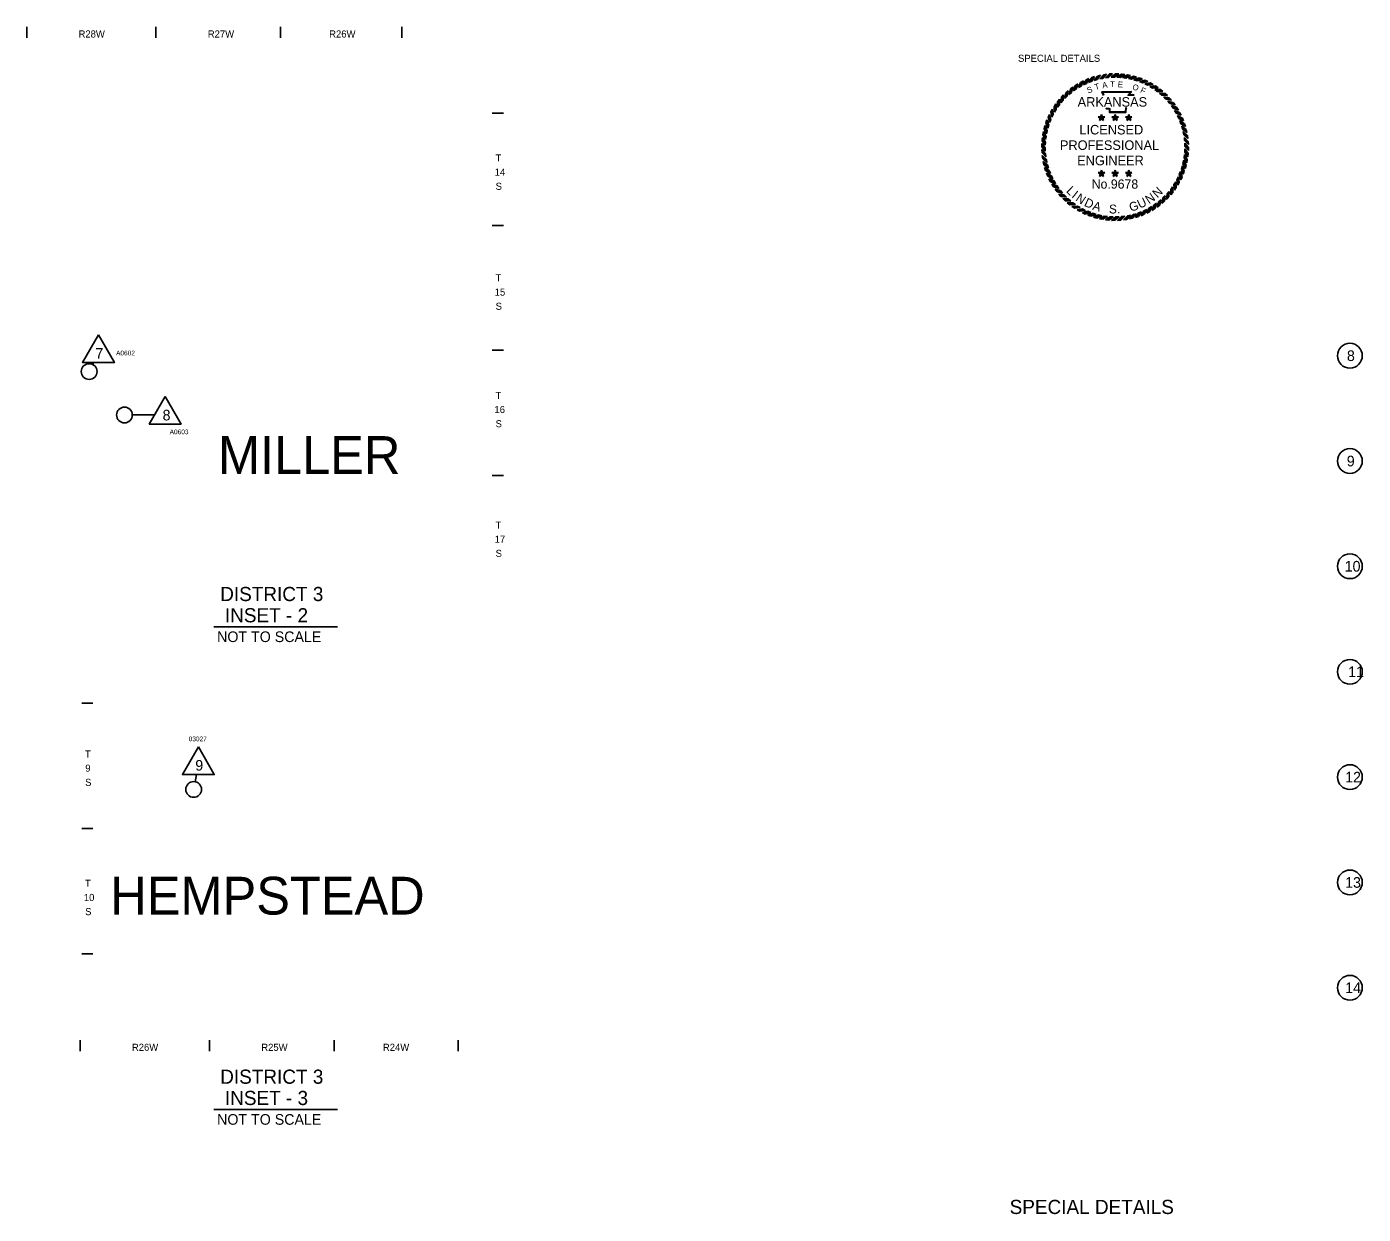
# Model space of a CAD drawing. Extents: x -17742 to 32032, y -17264 to 5867.
# Drawn here: x 7189 to 18510, y -4264 to 5793 of the extents above; entities that cross this region are included whole.
import ezdxf

# ---------------------------------------------------------------- set-up
doc = ezdxf.new("R2010")
doc.units = 0
for name, color, linetype in [('2', 7, 'Continuous'), ('Default', 7, 'Continuous'), ('R_Annotation', 7, 'Continuous'), ('R_Border', 7, 'Continuous'), ('R_No Plot', 7, 'Continuous'), ('STAMP', 7, 'Continuous')]:
    doc.layers.add(name, color=color, linetype=linetype)

msp = doc.modelspace()

# ---------------------------------------------------------------- linework, layer by layer
at = {"layer": 'Default'}
for p, q in [((7189, 5793), (7189, 5698)), ((8284, 5793), (8284, 5698)), ((9340, 5793), (9340, 5698)), ((10367, 5793), (10367, 5698)), ((11227, 5062), (11132, 5062)), ((11227, 4110), (11132, 4110)), ((11227, 3054), (11132, 3054)), ((11227, 1992), (11132, 1992)), ((7750, 65), (7655, 65)), ((7750, -997), (7655, -997)), ((7750, -2058), (7655, -2058)), ((7642, -2789), (7642, -2884)), ((8737, -2789), (8737, -2884)), ((9793, -2789), (9793, -2884)), ((10843, -2789), (10843, -2884))]:
    msp.add_line(p, q, dxfattribs=at)
at = {"layer": 'R_Annotation'}
for p, q in [((7748, 2933), (7756, 2949)), ((8083, 2505), (8272, 2505)), ((8773, 711), (9823, 711)), ((8616, -601), (8628, -539)), ((8773, -3377), (9823, -3377))]:
    msp.add_line(p, q, dxfattribs=at)
for points in [[(7797, 3183), (7932, 2949), (7662, 2949)], [(8362, 2662), (8497, 2428), (8227, 2428)], [(8643, -306), (8778, -540), (8508, -540)]]:
    msp.add_lwpolyline(points, close=True, dxfattribs=at)
for centre, radius in [((18397, 3007), 105), ((7718, 2873), 66.7), ((8017, 2505), 66.7), ((18397, 2115), 105), ((18397, 1224), 105), ((18397, 330), 105), ((18397, -562), 105), ((8603, -666), 66.7), ((18397, -1454), 105), ((18397, -2346), 105)]:
    msp.add_circle(centre, radius, dxfattribs=at)
at = {"layer": 'STAMP'}
for p, q in [((16116, 5321), (16140, 5334)), ((16162, 5343), (16187, 5355)), ((16184, 5322), (16210, 5331)), ((16210, 5362), (16235, 5371)), ((16230, 5339), (16257, 5346)), ((16259, 5376), (16285, 5383)), ((16278, 5352), (16305, 5356)), ((16309, 5387), (16336, 5391)), ((16326, 5360), (16353, 5363)), ((16360, 5393), (16387, 5395)), ((16375, 5365), (16402, 5365)), ((16412, 5394), (16439, 5394)), ((16423, 5366), (16451, 5364)), ((16463, 5392), (16490, 5390)), ((16472, 5363), (16499, 5358)), ((16513, 5385), (16540, 5381)), ((16521, 5355), (16547, 5349)), ((16564, 5375), (16590, 5368)), ((16568, 5344), (16594, 5335)), ((16613, 5360), (16638, 5351)), ((16615, 5329), (16640, 5318)), ((16660, 5341), (16685, 5330)), ((15954, 5197), (15972, 5217)), ((15990, 5233), (16010, 5251)), ((16019, 5220), (16040, 5237)), ((16030, 5266), (16051, 5282)), ((16057, 5250), (16079, 5266)), ((16072, 5295), (16094, 5310)), ((16097, 5278), (16121, 5291)), ((16140, 5302), (16165, 5313)), ((16660, 5310), (16684, 5297)), ((16703, 5287), (16726, 5273)), ((16706, 5318), (16730, 5305)), ((16745, 5261), (16766, 5245)), ((16750, 5292), (16773, 5277)), ((16784, 5232), (16804, 5213)), ((16792, 5262), (16813, 5245)), ((16831, 5228), (16851, 5210)), ((15864, 5072), (15877, 5096)), ((15891, 5116), (15905, 5139)), ((15921, 5158), (15937, 5179)), ((15921, 5111), (15938, 5132)), ((15950, 5150), (15969, 5170)), ((15983, 5186), (16003, 5205)), ((16820, 5199), (16839, 5179)), ((16854, 5164), (16871, 5142)), ((16867, 5192), (16885, 5172)), ((16885, 5126), (16900, 5103)), ((16900, 5153), (16917, 5131)), ((16929, 5111), (16944, 5088)), ((15822, 4978), (15831, 5004)), ((15841, 5026), (15852, 5051)), ((15853, 4981), (15864, 5006)), ((15872, 5026), (15885, 5050)), ((15895, 5069), (15910, 5092)), ((16320, 5031), (16265, 5031)), ((16265, 5031), (16310, 4999)), ((16293, 5051), (16276, 4999)), ((16276, 4999), (16320, 5031)), ((16289, 5022), (16297, 5022)), ((16310, 4999), (16293, 5051)), ((16293, 5025), (16293, 5018)), ((16436, 5031), (16381, 5031)), ((16381, 5031), (16425, 4999)), ((16408, 5051), (16391, 4999)), ((16391, 4999), (16436, 5031)), ((16404, 5022), (16412, 5022)), ((16425, 4999), (16408, 5051)), ((16408, 5025), (16408, 5018)), ((16551, 5031), (16496, 5031)), ((16496, 5031), (16541, 4999)), ((16524, 5051), (16507, 4999)), ((16507, 4999), (16551, 5031)), ((16520, 5022), (16528, 5022)), ((16541, 4999), (16524, 5051)), ((16524, 5025), (16524, 5018)), ((16912, 5085), (16925, 5061)), ((16936, 5042), (16947, 5017)), ((16955, 5067), (16969, 5043)), ((16956, 4998), (16965, 4972)), ((16978, 5020), (16989, 4996)), ((15797, 4879), (15801, 4906)), ((15808, 4929), (15814, 4956)), ((15827, 4886), (15833, 4913)), ((15838, 4934), (15847, 4960)), ((16973, 4952), (16980, 4925)), ((16986, 4905), (16990, 4878)), ((16996, 4972), (17005, 4947)), ((17010, 4923), (17017, 4897)), ((17021, 4873), (17025, 4846)), ((15788, 4777), (15788, 4804)), ((15790, 4828), (15792, 4856)), ((15816, 4789), (15818, 4816)), ((15817, 4740), (15817, 4768)), ((15820, 4838), (15824, 4865)), ((16995, 4856), (16997, 4829)), ((17000, 4759), (16998, 4732)), ((16999, 4808), (17000, 4780)), ((17027, 4822), (17029, 4795)), ((17029, 4771), (17029, 4744)), ((15790, 4726), (15787, 4753)), ((15796, 4675), (15791, 4702)), ((15806, 4625), (15799, 4651)), ((15822, 4692), (15819, 4719)), ((15831, 4643), (15826, 4670)), ((16990, 4662), (16983, 4635)), ((16997, 4710), (16993, 4683)), ((17020, 4669), (17015, 4642)), ((17026, 4720), (17024, 4692)), ((15820, 4576), (15811, 4601)), ((15839, 4528), (15828, 4552)), ((15843, 4596), (15836, 4623)), ((15860, 4550), (15851, 4576)), ((15880, 4506), (15869, 4531)), ((16320, 4558), (16265, 4558)), ((16265, 4558), (16310, 4525)), ((16293, 4578), (16276, 4526)), ((16276, 4526), (16320, 4558)), ((16289, 4549), (16297, 4549)), ((16310, 4526), (16293, 4578)), ((16293, 4552), (16293, 4545)), ((16436, 4558), (16381, 4558)), ((16381, 4558), (16425, 4525)), ((16408, 4578), (16391, 4526)), ((16391, 4526), (16436, 4558)), ((16404, 4549), (16412, 4549)), ((16425, 4526), (16408, 4578)), ((16408, 4552), (16408, 4545)), ((16551, 4558), (16496, 4558)), ((16496, 4558), (16541, 4525)), ((16524, 4578), (16507, 4526)), ((16507, 4526), (16551, 4558)), ((16520, 4549), (16528, 4549)), ((16541, 4526), (16524, 4578)), ((16524, 4552), (16524, 4545)), ((16963, 4567), (16952, 4542)), ((16978, 4614), (16970, 4588)), ((16994, 4570), (16985, 4544)), ((17009, 4619), (17002, 4592)), ((15861, 4481), (15848, 4505)), ((15887, 4437), (15872, 4460)), ((15904, 4463), (15891, 4487)), ((15917, 4395), (15900, 4417)), ((15932, 4422), (15917, 4445)), ((16895, 4438), (16879, 4416)), ((16922, 4479), (16907, 4456)), ((16926, 4432), (16911, 4409)), ((16944, 4522), (16931, 4498)), ((16952, 4476), (16940, 4452)), ((16975, 4522), (16964, 4497)), ((15950, 4356), (15931, 4376)), ((15962, 4384), (15945, 4406)), ((15986, 4320), (15965, 4338)), ((15996, 4349), (15977, 4369)), ((16025, 4286), (16003, 4303)), ((16033, 4316), (16012, 4335)), ((16072, 4287), (16050, 4303)), ((16798, 4328), (16777, 4311)), ((16826, 4315), (16806, 4297)), ((16833, 4362), (16813, 4343)), ((16863, 4351), (16844, 4331)), ((16866, 4398), (16848, 4378)), ((16896, 4390), (16879, 4369)), ((16066, 4256), (16043, 4271)), ((16110, 4230), (16086, 4243)), ((16113, 4261), (16090, 4275)), ((16156, 4207), (16131, 4218)), ((16156, 4238), (16132, 4251)), ((16202, 4219), (16177, 4230)), ((16204, 4188), (16178, 4197)), ((16248, 4204), (16222, 4213)), ((16296, 4193), (16269, 4199)), ((16344, 4185), (16317, 4190)), ((16539, 4196), (16512, 4192)), ((16586, 4209), (16560, 4202)), ((16632, 4226), (16606, 4217)), ((16655, 4205), (16630, 4193)), ((16677, 4246), (16652, 4235)), ((16701, 4227), (16677, 4214)), ((16719, 4270), (16695, 4257)), ((16745, 4253), (16722, 4238)), ((16760, 4298), (16737, 4282)), ((16787, 4282), (16765, 4266)), ((16253, 4173), (16226, 4180)), ((16303, 4163), (16276, 4167)), ((16354, 4156), (16327, 4158)), ((16393, 4182), (16366, 4184)), ((16405, 4154), (16378, 4153)), ((16442, 4183), (16415, 4183)), ((16456, 4155), (16429, 4153)), ((16491, 4188), (16463, 4185)), ((16507, 4162), (16480, 4157)), ((16557, 4172), (16531, 4165)), ((16607, 4186), (16581, 4177))]:
    msp.add_line(p, q, dxfattribs=at)
for points in [[(16097, 5278), (16116, 5321)], [(16105, 5282), (16123, 5325)], [(16113, 5287), (16132, 5330)], [(16121, 5291), (16140, 5334)], [(16140, 5302), (16162, 5343)], [(16148, 5305), (16170, 5347)], [(16156, 5309), (16178, 5351)], [(16165, 5313), (16187, 5355)], [(16184, 5322), (16210, 5362)], [(16193, 5325), (16218, 5365)], [(16202, 5328), (16227, 5368)], [(16210, 5331), (16235, 5371)], [(16230, 5339), (16259, 5376)], [(16239, 5341), (16267, 5378)], [(16248, 5344), (16277, 5381)], [(16257, 5346), (16285, 5383)], [(16278, 5352), (16309, 5386)], [(16286, 5353), (16318, 5388)], [(16296, 5355), (16327, 5390)], [(16305, 5356), (16336, 5391)], [(16326, 5360), (16360, 5393)], [(16335, 5361), (16369, 5393)], [(16344, 5362), (16378, 5394)], [(16353, 5363), (16387, 5395)], [(16374, 5365), (16412, 5394)], [(16383, 5365), (16420, 5394)], [(16393, 5365), (16430, 5394)], [(16402, 5365), (16439, 5394)], [(16423, 5366), (16463, 5392)], [(16432, 5365), (16471, 5391)], [(16442, 5365), (16481, 5391)], [(16451, 5364), (16490, 5390)], [(16472, 5363), (16513, 5385)], [(16481, 5361), (16522, 5384)], [(16490, 5360), (16531, 5383)], [(16499, 5358), (16540, 5381)], [(16521, 5355), (16564, 5375)], [(16529, 5353), (16572, 5373)], [(16538, 5351), (16581, 5370)], [(16547, 5349), (16590, 5368)], [(16568, 5344), (16613, 5360)], [(16577, 5341), (16621, 5357)], [(16586, 5338), (16630, 5354)], [(16594, 5335), (16639, 5351)], [(16615, 5329), (16660, 5341)], [(16623, 5325), (16668, 5337)], [(16632, 5322), (16677, 5334)], [(16640, 5318), (16685, 5330)], [(15963, 5163), (15966, 5210)], [(15969, 5170), (15972, 5217)], [(15983, 5186), (15990, 5233)], [(15989, 5192), (15997, 5239)], [(15996, 5199), (16004, 5245)], [(16003, 5205), (16010, 5251)], [(16019, 5220), (16030, 5266)], [(16025, 5225), (16037, 5271)], [(16033, 5231), (16044, 5277)], [(16040, 5237), (16051, 5283)], [(16057, 5250), (16071, 5295)], [(16064, 5255), (16079, 5300)], [(16072, 5261), (16087, 5305)], [(16079, 5266), (16094, 5310)], [(16310, 5212), (16296, 5243), (16547, 5244), (16526, 5217), (16543, 5217), (16557, 5218), (16571, 5216)], [(16314, 5214), (16302, 5239), (16538, 5240), (16517, 5213), (16543, 5213), (16557, 5214), (16571, 5212)], [(16660, 5310), (16706, 5318)], [(16668, 5306), (16714, 5314)], [(16676, 5302), (16722, 5310)], [(16684, 5297), (16730, 5305)], [(16703, 5287), (16750, 5292)], [(16711, 5283), (16757, 5287)], [(16719, 5278), (16766, 5282)], [(16726, 5273), (16773, 5277)], [(16745, 5261), (16792, 5262)], [(16752, 5256), (16799, 5256)], [(16759, 5250), (16806, 5251)], [(16766, 5245), (16813, 5245)], [(16784, 5232), (16831, 5228)], [(16790, 5226), (16837, 5222)], [(16797, 5220), (16844, 5216)], [(16804, 5213), (16851, 5210)], [(15885, 5050), (15877, 5096)], [(15895, 5069), (15891, 5116)], [(15900, 5076), (15895, 5123)], [(15905, 5084), (15900, 5131)], [(15910, 5092), (15905, 5139)], [(15921, 5110), (15921, 5158)], [(15926, 5117), (15926, 5164)], [(15932, 5125), (15931, 5172)], [(15938, 5132), (15937, 5179)], [(15950, 5150), (15954, 5197)], [(15956, 5156), (15960, 5203)], [(16507, 5107), (16503, 5103), (16501, 5098), (16500, 5085), (16500, 5068), (16360, 5068), (16360, 5091), (16360, 5096), (16354, 5098), (16334, 5098), (16331, 5104)], [(16505, 5110), (16499, 5106), (16498, 5099), (16496, 5085), (16496, 5072), (16364, 5072), (16364, 5091), (16364, 5099), (16355, 5102), (16337, 5102), (16334, 5106)], [(16820, 5199), (16867, 5192)], [(16826, 5193), (16873, 5185)], [(16833, 5186), (16879, 5179)], [(16839, 5179), (16885, 5172)], [(16854, 5164), (16900, 5153)], [(16859, 5157), (16905, 5146)], [(16865, 5150), (16911, 5138)], [(16871, 5142), (16917, 5131)], [(16885, 5126), (16929, 5111)], [(16889, 5118), (16934, 5103)], [(16895, 5110), (16940, 5096)], [(16900, 5103), (16944, 5088)], [(15841, 4942), (15825, 4987)], [(15844, 4951), (15828, 4996)], [(15847, 4960), (15831, 5004)], [(15853, 4981), (15841, 5026)], [(15857, 4989), (15845, 5034)], [(15860, 4997), (15848, 5043)], [(15864, 5006), (15852, 5051)], [(15872, 5026), (15864, 5072)], [(15876, 5033), (15868, 5080)], [(15881, 5042), (15872, 5088)], [(16912, 5085), (16955, 5067)], [(16916, 5077), (16960, 5059)], [(16921, 5069), (16964, 5051)], [(16925, 5061), (16969, 5043)], [(16936, 5042), (16978, 5020)], [(16940, 5034), (16981, 5012)], [(16944, 5026), (16985, 5004)], [(16947, 5017), (16989, 4996)], [(16956, 4998), (16996, 4972)], [(16959, 4990), (16999, 4964)], [(15820, 4838), (15797, 4879)], [(15821, 4847), (15798, 4888)], [(15822, 4856), (15799, 4897)], [(15824, 4865), (15801, 4906)], [(15827, 4886), (15808, 4929)], [(15829, 4895), (15810, 4938)], [(15831, 4904), (15812, 4947)], [(15833, 4913), (15814, 4956)], [(15838, 4934), (15822, 4978)], [(16963, 4981), (17002, 4955)], [(16965, 4972), (17005, 4947)], [(16973, 4952), (17010, 4923)], [(16975, 4943), (17013, 4915)], [(16978, 4934), (17015, 4906)], [(16980, 4925), (17017, 4897)], [(16986, 4905), (17021, 4873)], [(16987, 4896), (17022, 4864)], [(16989, 4887), (17024, 4855)], [(16991, 4878), (17025, 4846)], [(15817, 4768), (15788, 4804)], [(15817, 4758), (15788, 4795)], [(15817, 4749), (15788, 4786)], [(15817, 4740), (15788, 4777)], [(15816, 4789), (15790, 4828)], [(15818, 4807), (15791, 4847)], [(15817, 4798), (15791, 4837)], [(15818, 4816), (15792, 4856)], [(16995, 4856), (17027, 4822)], [(16995, 4848), (17027, 4813)], [(16996, 4838), (17029, 4804)], [(16997, 4829), (17029, 4795)], [(16999, 4808), (17029, 4771)], [(16999, 4799), (17029, 4762)], [(17000, 4790), (17029, 4753)], [(17000, 4780), (17029, 4744)], [(17000, 4759), (17026, 4720)], [(15819, 4719), (15787, 4753)], [(15820, 4710), (15788, 4744)], [(15821, 4700), (15789, 4735)], [(15822, 4692), (15790, 4726)], [(15826, 4670), (15791, 4702)], [(15827, 4661), (15792, 4693)], [(15829, 4652), (15794, 4684)], [(15831, 4643), (15796, 4675)], [(15836, 4623), (15799, 4651)], [(15839, 4614), (15801, 4642)], [(16985, 4644), (17005, 4601)], [(16987, 4653), (17007, 4610)], [(16990, 4662), (17009, 4619)], [(16993, 4683), (17015, 4642)], [(16994, 4692), (17017, 4651)], [(16995, 4701), (17018, 4660)], [(16997, 4710), (17020, 4669)], [(16998, 4732), (17024, 4692)], [(16999, 4750), (17026, 4711)], [(16999, 4741), (17025, 4701)], [(15841, 4605), (15804, 4633)], [(15843, 4596), (15806, 4625)], [(15851, 4576), (15811, 4601)], [(15854, 4567), (15814, 4593)], [(15857, 4558), (15818, 4584)], [(15860, 4550), (15820, 4576)], [(15869, 4531), (15828, 4553)], [(15873, 4522), (15831, 4544)], [(15877, 4514), (15835, 4536)], [(16952, 4542), (16964, 4497)], [(16956, 4551), (16968, 4505)], [(16960, 4559), (16972, 4514)], [(16963, 4567), (16975, 4522)], [(16970, 4588), (16985, 4544)], [(16973, 4597), (16988, 4552)], [(16975, 4606), (16991, 4561)], [(16978, 4614), (16994, 4570)], [(16983, 4635), (17002, 4592)], [(15880, 4506), (15839, 4528)], [(15891, 4487), (15848, 4505)], [(15895, 4479), (15852, 4497)], [(15900, 4471), (15857, 4489)], [(15904, 4463), (15861, 4481)], [(15917, 4445), (15872, 4460)], [(15922, 4438), (15877, 4452)], [(15927, 4430), (15882, 4445)], [(15932, 4422), (15887, 4437)], [(15945, 4406), (15900, 4417)], [(16879, 4416), (16879, 4369)], [(16884, 4423), (16885, 4376)], [(16890, 4431), (16891, 4384)], [(16895, 4438), (16896, 4390)], [(16907, 4456), (16911, 4409)], [(16912, 4464), (16916, 4417)], [(16917, 4472), (16921, 4425)], [(16922, 4479), (16926, 4432)], [(16931, 4498), (16940, 4452)], [(16936, 4506), (16944, 4460)], [(16940, 4515), (16948, 4468)], [(16944, 4522), (16952, 4476)], [(15951, 4399), (15905, 4410)], [(15957, 4391), (15911, 4402)], [(15962, 4384), (15917, 4395)], [(15977, 4369), (15931, 4376)], [(15984, 4362), (15937, 4369)], [(15990, 4355), (15944, 4363)], [(15996, 4349), (15950, 4356)], [(16012, 4335), (15965, 4338)], [(16019, 4328), (15972, 4332)], [(16026, 4322), (15979, 4326)], [(16033, 4316), (15986, 4320)], [(16050, 4303), (16003, 4303)], [(16777, 4311), (16765, 4266)], [(16784, 4317), (16773, 4271)], [(16791, 4323), (16780, 4277)], [(16798, 4328), (16787, 4282)], [(16814, 4343), (16806, 4297)], [(16820, 4349), (16813, 4303)], [(16827, 4356), (16820, 4310)], [(16833, 4362), (16826, 4315)], [(16848, 4378), (16844, 4331)], [(16854, 4385), (16850, 4338)], [(16860, 4392), (16857, 4345)], [(16866, 4398), (16863, 4352)], [(16057, 4298), (16010, 4297)], [(16065, 4292), (16018, 4292)], [(16072, 4287), (16025, 4286)], [(16090, 4275), (16043, 4271)], [(16098, 4270), (16051, 4266)], [(16106, 4265), (16059, 4261)], [(16113, 4261), (16066, 4256)], [(16132, 4251), (16086, 4243)], [(16140, 4246), (16094, 4238)], [(16149, 4242), (16102, 4234)], [(16157, 4238), (16110, 4230)], [(16177, 4230), (16131, 4218)], [(16185, 4226), (16139, 4214)], [(16194, 4223), (16148, 4211)], [(16202, 4219), (16156, 4207)], [(16222, 4213), (16178, 4197)], [(16231, 4210), (16186, 4194)], [(16240, 4207), (16196, 4191)], [(16248, 4204), (16204, 4188)], [(16269, 4199), (16226, 4180)], [(16278, 4197), (16235, 4178)], [(16287, 4195), (16244, 4176)], [(16296, 4193), (16253, 4173)], [(16317, 4190), (16276, 4167)], [(16512, 4192), (16480, 4157)], [(16521, 4193), (16489, 4158)], [(16530, 4195), (16499, 4160)], [(16539, 4197), (16507, 4162)], [(16560, 4202), (16531, 4165)], [(16568, 4204), (16540, 4167)], [(16578, 4207), (16549, 4170)], [(16586, 4209), (16557, 4172)], [(16606, 4217), (16581, 4177)], [(16615, 4220), (16590, 4180)], [(16624, 4223), (16598, 4183)], [(16632, 4226), (16607, 4186)], [(16652, 4235), (16630, 4193)], [(16660, 4239), (16638, 4197)], [(16669, 4243), (16647, 4201)], [(16677, 4246), (16655, 4205)], [(16695, 4257), (16677, 4214)], [(16703, 4261), (16685, 4218)], [(16712, 4266), (16693, 4223)], [(16719, 4270), (16701, 4227)], [(16737, 4282), (16722, 4238)], [(16745, 4287), (16730, 4243)], [(16752, 4293), (16738, 4248)], [(16760, 4298), (16745, 4253)], [(16326, 4188), (16285, 4165)], [(16336, 4187), (16294, 4164)], [(16344, 4185), (16303, 4163)], [(16366, 4184), (16327, 4158)], [(16375, 4183), (16336, 4157)], [(16384, 4183), (16345, 4157)], [(16393, 4182), (16354, 4156)], [(16415, 4183), (16378, 4153)], [(16424, 4183), (16387, 4153)], [(16433, 4183), (16396, 4154)], [(16442, 4183), (16405, 4154)], [(16463, 4185), (16429, 4153)], [(16473, 4186), (16438, 4154)], [(16482, 4187), (16448, 4155)], [(16491, 4188), (16456, 4155)]]:
    msp.add_lwpolyline(points, dxfattribs=at)

# ---------------------------------------------------------------- texts
at = {"layer": '2'}
for s, height, p in [('R28W', 60, (7628, 5702)), ('R27W', 60, (8723, 5702)), ('R26W', 60, (9751, 5702)), ('T', 60, (11160, 4652)), ('14', 60, (11153, 4532)), ('S', 60, (11161, 4412)), ('T', 60, (11160, 3636)), ('15', 60, (11153, 3516)), ('S', 60, (11161, 3396)), ('T', 60, (11160, 2641)), ('16', 60, (11151, 2521)), ('S', 60, (11161, 2401)), ('MILLER', 320, (8809, 2006)), ('T', 60, (11160, 1543)), ('17', 60, (11153, 1423)), ('S', 60, (11161, 1303)), ('T', 60, (7683, -396)), ('9', 60, (7685, -516)), ('S', 60, (7684, -636)), ('T', 60, (7683, -1491)), ('HEMPSTEAD', 320, (7897, -1726)), ('10', 60, (7673, -1611)), ('S', 60, (7684, -1731)), ('R26W', 60, (8080, -2880)), ('R25W', 60, (9176, -2880)), ('R24W', 60, (10206, -2880))]:
    msp.add_text(s, height=height, dxfattribs=at).set_placement(p)
at = {"layer": 'R_Annotation'}
for s, height, p in [('7', 90, (7771, 2982)), ('8', 90, (18372, 2962)), ('8', 90, (8340, 2459)), ('9', 90, (18371, 2070)), ('10', 90, (18353, 1179)), ('DISTRICT 3', 120, (8828, 929)), ('INSET - 2', 120, (8868, 749)), ('NOT TO SCALE', 90, (8802, 582)), ('11', 90, (18382, 285)), ('9', 90, (8617, -507)), ('12', 90, (18357, -607)), ('13', 90, (18357, -1499)), ('14', 90, (18357, -2391)), ('DISTRICT 3', 120, (8828, -3159)), ('INSET - 3', 120, (8868, -3339)), ('NOT TO SCALE', 90, (8802, -3506)), ('SPECIAL DETAILS', 120, (15515, -4262))]:
    msp.add_text(s, height=height, dxfattribs=at).set_placement(p)
at = {"layer": 'R_Border'}
msp.add_text('SPECIAL DETAILS', height=60, dxfattribs=at).set_placement((15586, 5496))
at = {"layer": 'R_No Plot'}
for s, p in [('A0602', (7946, 3010)), ('A0603', (8400, 2342)), ('03027', (8561, -258))]:
    msp.add_text(s, height=40, dxfattribs=at).set_placement(p)
at = {"layer": 'STAMP'}
for s, height, rotation, p in [('A', 49.5, 8.6788, (16303, 5272)), ('T', 49.5, 1.4789, (16367, 5282)), ('E', 49.5, 356.672, (16430, 5281)), ('S', 49.5, 19.7726, (16180, 5228)), ('T', 49.5, 16.9015, (16243, 5257)), ('O', 49.5, 341.2218, (16550, 5264)), ('F', 49.5, 335.3628, (16617, 5238)), ('L', 75.2, 315.1295, (15989, 4398)), ('N', 75.2, 42.6817, (16766, 4339)), ('I', 75.2, 321.696, (16035, 4352)), ('N', 75.2, 326.0736, (16068, 4325)), ('D', 75.2, 334.8288, (16140, 4279)), ('A', 75.2, 342.8544, (16212, 4246)), ('G', 75.2, 16.7808, (16540, 4226)), ('U', 75.2, 25.1712, (16618, 4251)), ('N', 75.2, 33.9264, (16695, 4289)), ('S', 75.2, 357.8112, (16355, 4213)), ('.', 75.2, 5.1072, (16426, 4211))]:
    msp.add_text(s, height=height, rotation=rotation, dxfattribs=at).set_placement(p)
for s, height, p in [('ARKANSAS', 80.8, (16091, 5116)), ('LICENSED', 80.8, (16106, 4881)), ('PROFESSIONAL', 80.77, (15941, 4750)), ('ENGINEER', 80.8, (16087, 4620)), ('No.9678', 77.9, (16210, 4422))]:
    msp.add_text(s, height=height, dxfattribs=at).set_placement(p)

doc.saveas('drawing.dxf')
